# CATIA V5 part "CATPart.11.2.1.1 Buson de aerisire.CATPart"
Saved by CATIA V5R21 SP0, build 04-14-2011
Part number: Buşon de aerisire
Bounding box of the stored display mesh (mm): x 0 to 19, y -8.698 to 8.698, z -9.806 to 9.806
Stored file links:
  C:\Users\MIRCEA\Desktop\MOM\Mogan\model\CATPart.11.2.1.1 Buson de aerisire.CATPart
  C:\Program Files\Dassault Systemes\B21\win_b64\reffiles\standard\MetricThinPitch.txt
  C:\Program Files\Dassault Systemes\B21\win_b64\reffiles\standard\MetricThickPitch.txt
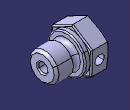
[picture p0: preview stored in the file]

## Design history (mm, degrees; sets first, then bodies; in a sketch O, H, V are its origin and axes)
Parameters
  d = 12 mm
  D = 16 mm
  L = 19 mm
  l = 10 mm
  d1 = 4 mm
  a = 2 mm
  S = 17 mm
Body1 (main body)
  Sketch1 on xy-plane, origin (0, 0, 0), H (1, 0, 0), V (0, 1, 0)
    line L1 (0, 0) -> (0, 8.5)
    point P1 (0, 8.5)
    line L2 (0, 8.5) -> (0.4019, 10)
    line L3 (0.4019, 10) -> (7, 10)
    line L4 (7, 10) -> (7, 8)
    line L5 (7, 8) -> (9, 8)
    line L6 (9, 8) -> (9, 6)
    arc A1 centre (10.5, 6) radius 1.5 from (9, 6) to (12, 6) ccw
    point P8 (12, 6)
    line L7 (12, 6) -> (19, 6)
    line L8 (19, 6) -> (19, 2)
    line L9 (19, 2) -> (2.1547, 2)
    point P12 (1, 0)
    line L10 (1, 0) -> (0, 0)
    line L11 (2.1547, 2) -> (1, 0)
    angle L1 L2 = 15
    distance P1 O = 8.5 {= S/2}
    distance L3 L10 = 10 {= S/2 + 1.5 mm}
    distance L9 L10 = 2 {= d1/2}
    distance L7 L10 = 6 {= d/2}
    distance L6 L8 = 10 {= l}
    distance L8 L1 = 19 {= L}
    distance P12 L8 = 18 {= L- 1 mm}
    angle L11 L10 = 60
    distance P8 L6 = 3
    distance A1 L10 = 4.5 {= d/2-1.5 mm}
    length L5 = 2 {= a}
    distance L5 L10 = 8 {= D/2}
    vertical: L1 V, L4 V, L6 V, L8 V
    horizontal: L3 H, L5 H, L7 H, L9 H, L10 H
    tangency: A1 L6
    coincidence: P12 H
  Shaft1: profile Sketch1, axis Sketch1.H, angle 360
  Sketch2 on face of Shaft1 from Sketch1.L1, origin (0, 0, 0), H (0, -1, 0), V (0, 0, 1)
    point P1 (0.4108, -9.8064)
    point P2 (8.698, -4.5474)
    point P3 (8.2871, 5.259)
    point P4 (-0.4108, 9.8064)
    point P5 (-8.698, 4.5474)
    point P6 (-8.2871, -5.259)
    point P7 (4.5544, -7.1769)
    line L1 (0.4108, -9.8064) -> (8.698, -4.5474)
    line L2 (8.698, -4.5474) -> (8.2871, 5.259)
    line L3 (8.2871, 5.259) -> (-0.4108, 9.8064)
    line L4 (-0.4108, 9.8064) -> (-8.698, 4.5474)
    line L5 (-8.698, 4.5474) -> (-8.2871, -5.259)
    line L6 (-8.2871, -5.259) -> (0.4108, -9.8064)
    construction line L7 (0, 0) -> (4.5544, -7.1769)
    construction circle A1 centre (0, 0) radius 9.815
    construction arc A2 centre (-8.698, 4.5474) radius 9.815 from (-0.4108, 9.8064) to (-8.2871, -5.259) cw
    construction arc A3 centre (8.698, -4.5474) radius 9.815 from (8.2871, 5.259) to (0.4108, -9.8064) ccw
    distance L1 L4 = 17 {= S}
    coincidence: A1 P1, A1 P2, A1 P3, A1 P4, A1 P5, A1 P6, A2 O, A3 O
    midpoint: P7 L1
  Pocket1: profile Sketch2, direction (1, 0, 0), length 7 {= L-a-l}, outer side
  Chamfer1: length 1, angle 45, on edge [face of Shaft1 from Sketch1.L7 | face of Shaft1 from Sketch1.L8]
  Fillet1: radius 0.5, on edge [face of Pocket1 | face of Pocket1 from Sketch2.L2]; edge [face of Pocket1 | face of Pocket1 from Sketch2.L3]; edge [face of Pocket1 | face of Pocket1 from Sketch2.L1]; edge [face of Pocket1 | face of Pocket1 from Sketch2.L6]; edge [face of Pocket1 | face of Pocket1 from Sketch2.L4]; edge [face of Pocket1 | face of Pocket1 from Sketch2.L5]
  Sketch3 on face of Pocket1 from Sketch2.L5, origin (3.5846, 8.4887, -0.447), H (1, 0, 0), V (0, -0.0419, -0.9991)
    point P1 (-0.0844, 0)
    reference projected curve E1 from edge [face of Shaft1 from Sketch1.L2 | face of Pocket1 from Sketch2.L5]
    distance P1 E1 = 3.5 {= (L-a-l)/2}
    coincidence: P1 H
  Hole1: placed by Sketch3, at (3.5001, 8.4887, -0.447) direction (0, -0.9991, 0.0419), diameter 4 {= d1}, through (limit type 3)
  Chamfer2: length 0.5, angle 45, on edge [face of Hole1 | face of Pocket1 from Sketch2.L2]; edge [face of Shaft1 from Sketch1.L8 | face of Shaft1 from Sketch1.L9]
  Fillet2: radius 0.5, on edge [face of Shaft1 from Sketch1.L5 | face of Shaft1 from Sketch1.L6]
